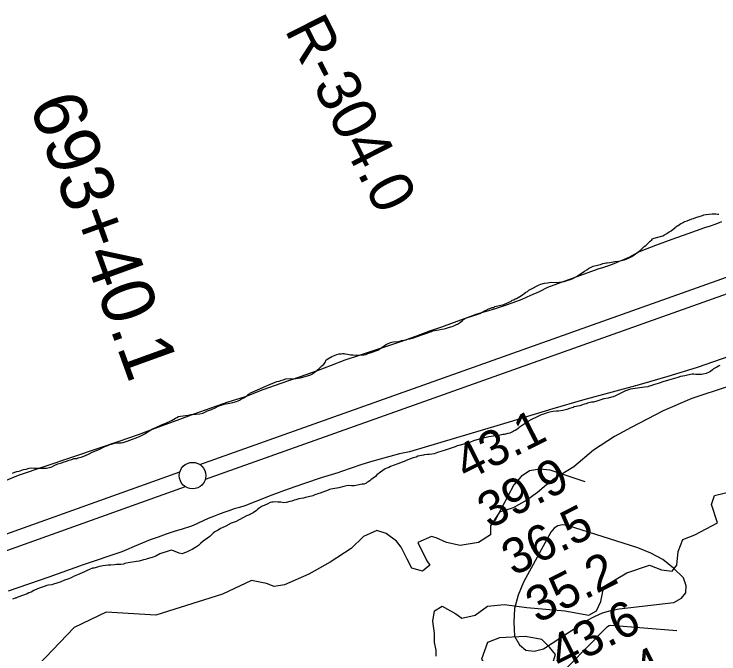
# Model space of a CAD drawing. Extents: x 3177385 to 3215275, y 903885 to 929304.
# Drawn here: x 3187679 to 3189007, y 913939 to 915145 of the extents above; entities that cross this region are included whole.
import ezdxf

# ---------------------------------------------------------------- set-up
doc = ezdxf.new("R2010")
doc.units = 0
for name, color, linetype in [('V-LEVE-TOET', 7, 'Continuous'), ('V-RIVR-RANG', 7, 'Continuous'), ('V-RIVR-RANG-IDEN', 7, 'Continuous'), ('V-SITE-VEGE', 7, 'Continuous'), ('V-SURV-IDEN', 7, 'Continuous'), ('V-SURV-LINE', 7, 'Continuous'), ('V-TOPO-MAJR', 7, 'Continuous'), ('V-TOPO-MINR', 7, 'Continuous')]:
    doc.layers.add(name, color=color, linetype=linetype)

msp = doc.modelspace()

# ---------------------------------------------------------------- linework, layer by layer
at = {"layer": 'V-LEVE-TOET'}
for points in [[(3187645.8, 914258.9), (3187687.1, 914275.7), (3187840.1, 914327.3), (3187876.9, 914339.8), (3187913.6, 914352.8), (3187950.2, 914366.2), (3187986.6, 914379.9), (3188018.5, 914391.7), (3188050.5, 914403), (3188082.7, 914413.9), (3188115.1, 914424.3), (3188148.8, 914437.1), (3188182.7, 914449.5), (3188216.8, 914461.5), (3188250.9, 914473), (3188277, 914483.4), (3188303.3, 914493.1), (3188329.8, 914502.2), (3188356.5, 914510.6), (3188383.2, 914519.5), (3188409.8, 914528.7), (3188436.2, 914538.1), (3188462.6, 914547.8), (3188485.1, 914555.5), (3188507.4, 914563.6), (3188529.7, 914571.8), (3188551.9, 914580.3), (3188569.2, 914584.8), (3188586.3, 914589.9), (3188603.2, 914595.4), (3188620, 914601.4), (3188636.7, 914607.9), (3188653.1, 914614.9), (3188669.3, 914622.3), (3188685.2, 914630.2), (3188780.2, 914664.6), (3188790.3, 914667.8), (3188800.3, 914671.3), (3188810.2, 914675), (3188820, 914679), (3188829.7, 914683.2), (3188839.3, 914687.7), (3188848.7, 914692.4), (3188858, 914697.4), (3188888.5, 914709.2), (3188919.1, 914720.6), (3188949.8, 914731.7), (3188980.7, 914742.4), (3188991.6, 914745.8), (3189002.3, 914749.7), (3189012.9, 914754.1)], [(3189135.2, 914537), (3188966.8, 914478.9), (3188964.9, 914478.2), (3188911.2, 914461.6), (3188857.2, 914446), (3188806.6, 914432.1), (3188750.4, 914417.1), (3188694.4, 914401.1), (3188638.8, 914384.1), (3188618.6, 914377.7), (3188618.6, 914377.7), (3188454, 914328.9), (3188424.2, 914320.2), (3188424.2, 914320.2), (3188405.7, 914315.9), (3188387.2, 914311.2), (3188368.9, 914306.2), (3188350.6, 914300.9), (3188332.4, 914295.2), (3188314.3, 914289.3), (3188296.4, 914283.1), (3188289, 914280.4), (3188257.7, 914270.7), (3188226.6, 914260.5), (3188195.7, 914249.7), (3188165, 914238.4), (3188134.5, 914226.5), (3188114.2, 914218.3), (3188104.1, 914215.3), (3188094.1, 914212.3), (3188084.1, 914209)], [(3188084.1, 914209), (3188074.2, 914205.5), (3188064.4, 914201.9), (3188054.6, 914198.2), (3188044.9, 914194.2), (3188035.3, 914190.1), (3188025.8, 914185.8), (3188016.3, 914181.4), (3188011.3, 914179), (3187996, 914174.4), (3187980.7, 914169.7), (3187965.5, 914164.6), (3187950.4, 914159.3), (3187935.3, 914153.8), (3187920.4, 914147.9), (3187905.6, 914141.8), (3187890.9, 914135.5), (3187882.1, 914131.5), (3187809.4, 914106.9), (3187744.6, 914083.8), (3187744.6, 914083.8), (3187667.8, 914057.4)]]:
    msp.add_lwpolyline(points, dxfattribs=at)
at = {"layer": 'V-SITE-VEGE'}
for points in [[(3188947.5, 914755.5), (3188956.7, 914759.1), (3188959.4, 914759.5), (3188964, 914761.3), (3188976.3, 914765.2), (3188979, 914766.3), (3188983.2, 914767), (3188995, 914768.2), (3188997.3, 914768.6), (3189001.5, 914768.5), (3189005.3, 914768), (3189007.6, 914767.6)], [(3188475.1, 914549.1), (3188479.7, 914549.8), (3188485, 914551.2), (3188489.6, 914551.8), (3188492.3, 914552.6), (3188498.1, 914554.3), (3188504.6, 914556.1), (3188507.7, 914557.6), (3188512.7, 914559.7), (3188514.6, 914560.5), (3188516.5, 914561.6), (3188518.5, 914563), (3188520.4, 914564.1), (3188524.3, 914567.5), (3188526.6, 914569.7), (3188529.7, 914572), (3188533.5, 914573.4), (3188541.6, 914575.9), (3188547.7, 914577.3), (3188557, 914580.9), (3188560, 914582.4), (3188563.9, 914584.6), (3188567, 914586), (3188568.9, 914587.1), (3188573.5, 914589.3), (3188575.8, 914590), (3188580.4, 914591.8), (3188583.1, 914592.2), (3188585.4, 914593.6), (3188599.6, 914597.1), (3188601.9, 914597.9), (3188608.8, 914600.8), (3188615.8, 914604), (3188618.1, 914605.5), (3188620.8, 914606.6), (3188623.5, 914608.1), (3188626.2, 914609.2), (3188635.4, 914614.7), (3188637.7, 914616.5), (3188640.1, 914618), (3188643.6, 914621), (3188646.6, 914622.4), (3188649.3, 914624.3), (3188656.7, 914628.3), (3188665.2, 914632.7), (3188669, 914634.5), (3188671.7, 914635.6), (3188679, 914637.8), (3188684.3, 914638.4), (3188688.2, 914639.1), (3188692.7, 914639.4), (3188701.5, 914639.2), (3188715.6, 914641.2), (3188723.3, 914643.3), (3188727.9, 914644.7), (3188731, 914646.2), (3188734.8, 914647.6), (3188739.1, 914650.6), (3188747.6, 914655.7), (3188754.2, 914660.2), (3188758.8, 914663.1), (3188761.9, 914665.3), (3188767.7, 914668.3), (3188770.8, 914670.1), (3188778.8, 914671.8), (3188781.1, 914672.6), (3188784.2, 914673.2), (3188788.8, 914674.7), (3188794.9, 914676.1), (3188797.2, 914676.4), (3188801.8, 914676.7), (3188804.8, 914677.4), (3188811.3, 914678.4), (3188818.2, 914679), (3188821.7, 914679.7), (3188824, 914680.8), (3188829.3, 914681.8), (3188835.8, 914684), (3188843.6, 914688), (3188854.4, 914696.1), (3188859.8, 914699.8), (3188866.8, 914706.6), (3188869.5, 914708.8), (3188871.1, 914710.3), (3188877.7, 914717), (3188880.8, 914719.2), (3188882.4, 914721.1), (3188885.5, 914722.9), (3188901.6, 914727.2), (3188905, 914729), (3188909.3, 914731.6), (3188913.5, 914734.5), (3188917.4, 914736.7), (3188924.7, 914742.3), (3188928.6, 914746), (3188930.6, 914746.7), (3188935.6, 914750.4), (3188938.7, 914751.5), (3188940.6, 914753), (3188943.3, 914754.1), (3188947.5, 914755.5)], [(3187940.2, 914363.5), (3187943.3, 914364.5), (3187946, 914365.6), (3187956.8, 914370.7), (3187962.1, 914372.5), (3187973.3, 914378), (3187976.8, 914379.4), (3187979.9, 914381.7), (3187983, 914383.5), (3187986, 914384.6), (3187989.1, 914386.4), (3187992.6, 914387.1), (3188007.1, 914389.1), (3188012.4, 914390.1), (3188014.7, 914390.5), (3188029.2, 914391.3), (3188035, 914393.1), (3188043.5, 914397.1), (3188051.1, 914399.6), (3188059.6, 914403.6), (3188063.9, 914405.8), (3188073.1, 914409.4), (3188077.7, 914410.1), (3188081.9, 914411.1), (3188084.9, 914411.4), (3188088.4, 914412.1), (3188091.1, 914413.2), (3188098, 914415), (3188101.4, 914416), (3188103.7, 914417.1), (3188107.6, 914419.7), (3188111.8, 914421.9), (3188117.6, 914425.6), (3188120.4, 914428.2), (3188123.1, 914429.7), (3188124.6, 914431.2), (3188127.7, 914432.6), (3188138.1, 914437), (3188153.5, 914443.9), (3188158.9, 914446.5), (3188169.6, 914450.4), (3188174.2, 914452.2), (3188178.8, 914453.3), (3188181.9, 914454.4), (3188186.1, 914455.4), (3188191.5, 914457.6), (3188199.9, 914458.2), (3188203.3, 914457.7), (3188210.9, 914458.3), (3188219, 914459.3), (3188225.1, 914461.1), (3188236.6, 914464.6), (3188241.6, 914467.2), (3188245.1, 914469.8), (3188249, 914472.4), (3188250.9, 914474.2), (3188254, 914476.8), (3188259.1, 914481.7), (3188263, 914485), (3188265.3, 914488), (3188267.3, 914493.3), (3188270.4, 914495.5), (3188277.8, 914499.6), (3188281.2, 914501), (3188287.4, 914503.2), (3188291.6, 914504.6), (3188295.4, 914504.5), (3188298.1, 914505.2), (3188300.4, 914505.2), (3188302.6, 914504.4), (3188307.2, 914503.9), (3188313.7, 914503), (3188317.8, 914502.5), (3188326.6, 914502.3), (3188338.4, 914502.8), (3188341.9, 914503.5), (3188344.2, 914504.6), (3188351.9, 914507.1), (3188360.7, 914510.4), (3188364.9, 914511.4), (3188366.8, 914512.9), (3188376.5, 914519.6), (3188378.8, 914521.4), (3188383.1, 914523.2), (3188388.5, 914525.8), (3188393.8, 914527.2), (3188403.4, 914527.8), (3188406.4, 914528.5), (3188409.5, 914529.5), (3188417.9, 914531.3), (3188420.6, 914532), (3188424.8, 914532.6), (3188426.7, 914533.4), (3188429.8, 914534.1), (3188447.5, 914540.5), (3188453.2, 914542.3), (3188458.6, 914544.1), (3188463.2, 914545.9), (3188465.5, 914547), (3188467.4, 914547.7), (3188475.1, 914549.1)], [(3189009.4, 914482.9), (3189006.7, 914481.4), (3189003.6, 914479.6), (3188997.5, 914476.6), (3188995.5, 914474.4), (3188991.7, 914471.4), (3188989, 914470.3), (3188983.6, 914467.8), (3188977.8, 914466), (3188974.4, 914465.7), (3188967.9, 914465.5), (3188963.7, 914465.5), (3188960.3, 914466), (3188956.9, 914466.1), (3188948.5, 914464.7), (3188943.1, 914463.3), (3188939.3, 914462.6), (3188935.4, 914461.6), (3188930.1, 914459.8), (3188925.5, 914458.7), (3188912.8, 914454.8), (3188902.1, 914452), (3188896.7, 914449.8), (3188892.8, 914448.8), (3188884.4, 914445.9), (3188879, 914444.5), (3188876.3, 914443.4), (3188873.3, 914442.7), (3188867.2, 914441.7), (3188854.2, 914440.1), (3188840.8, 914438.1), (3188837, 914437), (3188831.2, 914434.8), (3188825.4, 914431.5), (3188816.5, 914427.5), (3188812.3, 914425.3), (3188808.5, 914423.9), (3188805, 914422.8), (3188798.5, 914421), (3188790.5, 914419.7), (3188775.5, 914414.7), (3188773.2, 914414.3), (3188770.9, 914413.6), (3188767.1, 914413.3), (3188764.8, 914412.6), (3188759.8, 914411.6), (3188757.1, 914410.5), (3188753.7, 914409.8), (3188750.2, 914408.7), (3188745.2, 914406.9), (3188734.9, 914404.5), (3188732.6, 914403.4), (3188730.3, 914402.7), (3188725.7, 914401.6), (3188720.7, 914399.8), (3188713.4, 914397.7), (3188705.4, 914396.7), (3188701.2, 914396.8), (3188695.4, 914396.2), (3188691.6, 914395.1)], [(3189024.8, 914443), (3188956.4, 914420.2), (3188902.2, 914397.4), (3188842.3, 914366), (3188810.9, 914348.8), (3188771, 914323.1), (3188733.9, 914291.7), (3188696.8, 914268.9), (3188682.5, 914257.5), (3188665.4, 914243.2), (3188645.4, 914229), (3188619.8, 914214.7), (3188594.1, 914206.1), (3188577, 914180.4), (3188577, 914163.3), (3188554.2, 914149), (3188519.9, 914143.3), (3188494.2, 914149), (3188474.3, 914157.6), (3188465.7, 914160.5), (3188440, 914149), (3188457.2, 914114.8), (3188462.9, 914106.2), (3188448.6, 914094.8), (3188428.6, 914100.5), (3188420.1, 914117.6), (3188408.7, 914140.5), (3188400.1, 914151.9), (3188380.1, 914166.2), (3188363, 914171.9), (3188337.4, 914160.5), (3188314.5, 914137.6), (3188274.6, 914111.9), (3188234.7, 914089.1), (3188189, 914069.1), (3188169, 914066.3), (3188154.8, 914072), (3188126.3, 914077.7), (3188072.1, 914052), (3187946.5, 914012), (3187852.4, 914017.7)], [(3188691.6, 914395.1), (3188683.6, 914393.4), (3188676.7, 914391.2), (3188672.8, 914389.8), (3188669, 914387.6), (3188663.6, 914385.4), (3188654.3, 914381), (3188647.4, 914377), (3188644.3, 914374.4), (3188642.4, 914373.3), (3188635, 914368.1), (3188631.1, 914365.5), (3188629.2, 914363.7), (3188626.9, 914361.8), (3188623.4, 914360), (3188621.5, 914359.3), (3188619.6, 914358.2), (3188616.9, 914357.1), (3188613.4, 914355.2), (3188609.9, 914354.5), (3188603, 914352.8), (3188600.4, 914352.5), (3188595, 914351.4), (3188588.5, 914350.4), (3188582.8, 914349.4), (3188574, 914348.1), (3188569, 914347), (3188560.2, 914344.9), (3188545.2, 914340.7), (3188539.1, 914338.1), (3188531, 914336), (3188529.1, 914335.3), (3188517.2, 914331.7), (3188514.2, 914331.1), (3188510.3, 914329.2), (3188506.9, 914327.8), (3188503, 914326.7), (3188501.1, 914326), (3188489.6, 914322.4), (3188485, 914321.4), (3188476.9, 914318.9), (3188470.8, 914316.4), (3188466.6, 914315.7), (3188461.6, 914315), (3188458.2, 914314.7), (3188452.8, 914314.1), (3188450.5, 914313.4), (3188439.8, 914311.7), (3188436.7, 914310.2), (3188431.4, 914308.4), (3188418.3, 914303.4), (3188414.4, 914301.5), (3188412.5, 914300.8), (3188410.2, 914300.5), (3188402.2, 914297.2), (3188388.7, 914292.6), (3188385.2, 914290.4), (3188381.4, 914289.3), (3188378.7, 914287.8), (3188369.4, 914281.5), (3188362.8, 914276.3), (3188360.1, 914273.7), (3188351.6, 914267.4), (3188349.6, 914265.6), (3188346.2, 914263.4), (3188344.2, 914261.9), (3188341.9, 914260.4), (3188338.1, 914259.3), (3188335.4, 914259), (3188332, 914258.3), (3188329.3, 914257.6), (3188320.1, 914255.9), (3188314.8, 914256), (3188310.2, 914256.5), (3188305.6, 914255.8), (3188300.6, 914254.8), (3188291.1, 914252.3), (3188280, 914250.3), (3188275.8, 914249.6), (3188273.8, 914248.9), (3188271.1, 914247.4), (3188260.8, 914243.8), (3188256.2, 914242), (3188253.5, 914241.3), (3188246.2, 914238.8), (3188241.9, 914237), (3188228.5, 914234.2), (3188226.6, 914233.5), (3188224.3, 914232.8), (3188215.5, 914231.1), (3188210.1, 914229.3), (3188207.1, 914228.6), (3188202.5, 914227.2), (3188199, 914226.5), (3188192.1, 914224.3), (3188187.2, 914224.1), (3188181.8, 914224.9), (3188176.1, 914225.1), (3188170.4, 914225.6), (3188167, 914225.3), (3188164.7, 914225.3)], [(3187675.8, 914279.5), (3187680.5, 914281.7), (3187684.3, 914282.8), (3187687.7, 914283.5), (3187690.4, 914284.2), (3187697, 914286.7), (3187701.5, 914287.4), (3187707.7, 914289.1), (3187712.6, 914289.8), (3187717.6, 914288.9), (3187720.6, 914288.9), (3187735.1, 914289.3), (3187740.1, 914289.2), (3187742.4, 914289.5), (3187745.8, 914290.2), (3187750.4, 914291.7), (3187754.3, 914293.9), (3187761.6, 914297.1), (3187767.3, 914298.9), (3187771.6, 914300.7), (3187778.1, 914302.5), (3187783.1, 914304.3), (3187787.7, 914305.7), (3187791.9, 914307.2), (3187794.6, 914307.1), (3187797.3, 914307.4), (3187799.2, 914308.5), (3187805.7, 914309.9), (3187813.8, 914313.2), (3187820.3, 914316.1), (3187826.1, 914319.4), (3187840.7, 914325.2), (3187845.3, 914327.4), (3187848.8, 914329.2), (3187853.4, 914331), (3187855.7, 914331.7), (3187859.6, 914333.5), (3187862.6, 914334.6), (3187868, 914336), (3187874.5, 914336.7), (3187881, 914336.9), (3187884.4, 914337.6), (3187888.6, 914338.6), (3187892.1, 914340.1), (3187902.1, 914343.7), (3187909.4, 914346.2), (3187916.7, 914349.5), (3187925.2, 914353.9), (3187931.7, 914358.3), (3187940.2, 914363.5)], [(3188930.7, 914131.9), (3188939.3, 914154.7), (3188962.1, 914163.3), (3189004.9, 914186.1), (3188993.5, 914220.4), (3188999.2, 914237.5), (3189033.4, 914246.1)], [(3188164.7, 914225.3), (3188162, 914224.2), (3188157, 914221.7), (3188150.5, 914218.7), (3188146.6, 914217.3), (3188141.2, 914213.6), (3188137.7, 914211.4), (3188135.8, 914209.5), (3188129.6, 914205.1), (3188124.6, 914202.5), (3188122.7, 914201.4), (3188117.3, 914199.6), (3188104.6, 914192.7), (3188096.1, 914188.3), (3188093.8, 914187.6), (3188088, 914185.4), (3188078, 914179.9), (3188071.1, 914177), (3188068, 914175.5), (3188063.7, 914172.6), (3188057.6, 914168.9), (3188054.5, 914166.7), (3188048.2, 914160.7), (3188043.6, 914157), (3188035.5, 914151.8), (3188030.4, 914147.4), (3188026.5, 914143.6), (3188023, 914141), (3188019.6, 914139.2), (3188014.5, 914135.9), (3188011.8, 914134.4), (3188004.1, 914130.8), (3188000.3, 914129.3), (3187995.7, 914127.9), (3187990.4, 914128.8), (3187979.4, 914133.2), (3187974.9, 914134.4), (3187965.7, 914131.6), (3187959.2, 914129.8), (3187953.8, 914127.7), (3187946.1, 914123.6), (3187939.1, 914120.7), (3187936.5, 914120.4), (3187929.6, 914118.3), (3187926.9, 914117.2), (3187922.7, 914116.5), (3187915, 914114), (3187909.6, 914113), (3187893.9, 914110.6), (3187887.8, 914109.2), (3187885.5, 914108.5), (3187880.2, 914107.9), (3187872.2, 914107.7), (3187868, 914107), (3187861.1, 914106.4), (3187856.1, 914106.1), (3187846.6, 914105.2), (3187843.9, 914104.5), (3187839.7, 914103.8), (3187836.2, 914102.7), (3187829.3, 914101), (3187826.7, 914100.6), (3187821.3, 914098.5), (3187817, 914096.3), (3187814, 914095.2), (3187811.6, 914093.7), (3187798.6, 914088.3), (3187795.5, 914086.8), (3187790.9, 914085), (3187786.6, 914082.8), (3187780.1, 914080.3), (3187774, 914078.1), (3187765.9, 914074.5), (3187763.6, 914073.8), (3187759.7, 914072.3), (3187753.2, 914070.6), (3187750.1, 914069.5), (3187744, 914068.5), (3187741, 914067.8), (3187736, 914066), (3187727.9, 914063.5), (3187723.3, 914061.7), (3187716.4, 914058.8), (3187711.4, 914055.8), (3187706.8, 914054), (3187704, 914052.2), (3187686.4, 914046.1), (3187682.2, 914044.3), (3187681, 914044.3), (3187676, 914042.1)], [(3188474.3, 913935), (3188474.3, 913946.4), (3188471.4, 913960.6), (3188471.4, 913977.8), (3188468.6, 914000.6), (3188471.4, 914020.6), (3188485.7, 914029.2), (3188511.4, 914014.9), (3188522.8, 914006.3), (3188548.4, 914012), (3188571.3, 914029.2), (3188602.7, 914032), (3188645.4, 914026.3), (3188716.8, 914020.6), (3188762.4, 914012), (3188776.7, 914020.6), (3188785.2, 914037.7), (3188790.9, 914066.3), (3188833.7, 914091.9), (3188876.5, 914106.2), (3188899.3, 914097.7), (3188919.3, 914094.8), (3188927.9, 914106.2), (3188930.7, 914131.9)], [(3187852.4, 914017.7), (3187792.5, 913989.2), (3187738.3, 913932.1), (3187701.2, 913895), (3187675.5, 913883.6)]]:
    msp.add_lwpolyline(points, dxfattribs=at)
msp.add_lwpolyline([(3188642.6, 913972.1), (3188594.1, 913969.2), (3188571.3, 913960.6), (3188559.9, 913929.2), (3188574.1, 913909.3), (3188605.5, 913900.7), (3188654, 913906.4), (3188693.9, 913920.7), (3188699.6, 913937.8), (3188688.2, 913952.1), (3188674, 913966.4), (3188656.9, 913969.2)], close=True, dxfattribs=at)
at = {"layer": 'V-SURV-LINE'}
for points in [[(3188029.3, 914295.9), (3190382.2, 915132.8)], [(3190392.3, 915104.5), (3188039.3, 914267.6)], [(3185491.6, 913387), (3187991.6, 914282.5)], [(3188001.8, 914254.2), (3185501.7, 913358.7)]]:
    msp.add_lwpolyline(points, dxfattribs=at)
msp.add_circle((3188015.5, 914275.1), 25, dxfattribs=at)
at = {"layer": 'V-TOPO-MAJR'}
msp.add_lwpolyline([(3188945.4, 914054.1), (3188945.7, 914067.4), (3188940.5, 914082.8), (3188921.8, 914101), (3188901.6, 914116.9), (3188879.1, 914129.2), (3188855, 914139.1), (3188722.1, 914181.4), (3188712.7, 914182.2), (3188704.2, 914180.7), (3188697, 914175.8), (3188690.7, 914168.8), (3188639.2, 914074.1), (3188629.1, 914049.7), (3188622.3, 914024.8), (3188620.7, 913999), (3188622.5, 913972.7), (3188631.6, 913956.4), (3188643.4, 913946), (3188659, 913944.4), (3188677.2, 913948.8), (3188758.7, 914001.8), (3188773.1, 914009.8), (3188788, 914016.4), (3188803.6, 914020.8), (3188819.8, 914023.9), (3188922.4, 914036.2), (3188936.7, 914044.1), (3188945.4, 914054.1)], dxfattribs=at)
at = {"layer": 'V-TOPO-MINR'}
for points in [[(3188755.4, 914263.5), (3188689.7, 914285.4), (3188669.1, 914287.3), (3188650.5, 914284.2), (3188634.8, 914273.6), (3188621.2, 914258), (3188585, 914190)], [(3188689, 913880), (3188797.6, 913990.8), (3188800.4, 913992.7), (3188803.8, 913993.1), (3188928.4, 913983)]]:
    msp.add_lwpolyline(points, dxfattribs=at)

# ---------------------------------------------------------------- texts
at = {"layer": 'V-RIVR-RANG'}
for s, p in [('43.1', (3188531.8, 914264.4)), ('39.9', (3188574.8, 914174)), ('36.5', (3188620.3, 914085)), ('35.2', (3188665.7, 913995.9)), ('43.6', (3188709.3, 913905.9)), ('40.4', (3188756.3, 913817.6))]:
    msp.add_text(s, height=67, rotation=26.8183, dxfattribs=at).set_placement(p)
at = {"layer": 'V-RIVR-RANG-IDEN'}
msp.add_text('R-304.0', height=83, rotation=296.9575, dxfattribs=at).set_placement((3188188.1, 915115.3))
at = {"layer": 'V-SURV-IDEN'}
msp.add_text('693+40.1', height=100, rotation=289.8547, dxfattribs=at).set_placement((3187706.8, 914975.7))

doc.saveas('drawing.dxf')
